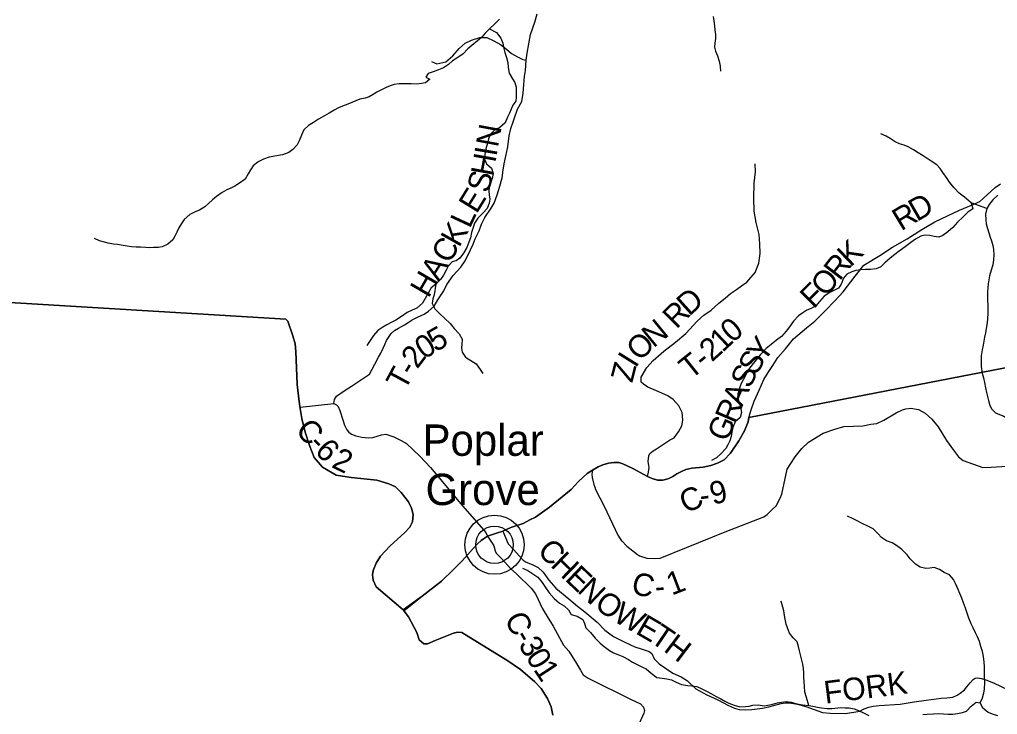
# Model space of a CAD drawing. Extents: x 1578669 to 1989827, y 208020 to 553079.
# Drawn here: x 1733554 to 1746556, y 378964 to 388207 of the extents above; entities that cross this region are included whole.
import ezdxf

# ---------------------------------------------------------------- set-up
doc = ezdxf.new("R2010")
doc.units = 0
for name, color, linetype in [('GM_X_Adjacent_County', 7, 'Continuous'), ('GM_X_County', 7, 'Continuous'), ('GM_X_County_Road', 7, 'Continuous'), ('GM_X_County_Road_Text', 7, 'Continuous'), ('GM_X_Minor_River', 7, 'Continuous'), ('GM_X_Township', 7, 'Continuous'), ('GM_X_Township_Road', 7, 'Continuous'), ('GM_X_Township_Road_Text', 7, 'Continuous'), ('GM_X_Unincorporated', 7, 'Continuous'), ('GM_X_Unincorporated_Location', 7, 'Continuous'), ('GM_X_Unincorporated_Text', 7, 'Continuous')]:
    doc.layers.add(name, color=color, linetype=linetype)

msp = doc.modelspace()

# ---------------------------------------------------------------- linework, layer by layer
at = {"layer": 'GM_X_Adjacent_County'}
msp.add_lwpolyline([(1733054, 384466), (1737094, 384224), (1737122, 384196), (1737189, 383999), (1737217, 383893), (1737228, 383790), (1737245, 383351), (1737272, 383125), (1737282, 383062), (1737309, 382900), (1737352, 382721), (1737408, 382543), (1737471, 382382), (1737581, 382255), (1737763, 382149), (1737961, 382114), (1738306, 382082), (1738462, 382031), (1738552, 381991), (1738628, 381917), (1738723, 381794), (1738765, 381710), (1738789, 381625), (1738780, 381525), (1738744, 381457), (1738678, 381385), (1738477, 381203), (1738354, 381068), (1738297, 380978), (1738257, 380880), (1738247, 380819), (1738256, 380749), (1738296, 380661), (1738653, 380354), (1738727, 380263), (1738834, 380056), (1738869, 379957), (1738928, 379905), (1738978, 379902), (1739079, 379949), (1739322, 380047), (1739378, 380057), (1739434, 380055), (1740048, 379676), (1740214, 379563), (1740405, 379400), (1740489, 379311), (1740575, 379176), (1740620, 379064), (1740644, 378956)], dxfattribs=at)
at = {"layer": 'GM_X_County'}
msp.add_lwpolyline([(1740644, 378956), (1740620, 379064), (1740575, 379176), (1740489, 379311), (1740405, 379400), (1740214, 379563), (1740048, 379676), (1739434, 380055), (1739378, 380057), (1739322, 380047), (1739079, 379949), (1738978, 379902), (1738928, 379905), (1738869, 379957), (1738834, 380056), (1738727, 380263), (1738653, 380354), (1738296, 380661), (1738256, 380749), (1738247, 380819), (1738257, 380880), (1738297, 380978), (1738354, 381068), (1738477, 381203), (1738678, 381385), (1738744, 381457), (1738780, 381525), (1738789, 381625), (1738765, 381710), (1738723, 381794), (1738628, 381917), (1738552, 381991), (1738462, 382031), (1738306, 382082), (1737961, 382114), (1737763, 382149), (1737581, 382255), (1737471, 382382), (1737408, 382543), (1737352, 382721), (1737309, 382900), (1737282, 383062), (1737272, 383125), (1737245, 383351), (1737228, 383790), (1737217, 383893), (1737189, 383999), (1737122, 384196), (1737094, 384224), (1733054, 384466)], dxfattribs=at)
at = {"layer": 'GM_X_County_Road'}
for points in [[(1743283, 383014), (1743321, 383133), (1743389, 383278), (1743449, 383418), (1743509, 383512), (1743569, 383606), (1743638, 383711), (1743736, 383829), (1743846, 383959), (1744016, 384106), (1744126, 384196), (1744266, 384334), (1744393, 384465), (1744505, 384587), (1744665, 384794), (1744779, 384940), (1744991, 385070), (1745162, 385181), (1745358, 385289), (1745552, 385416), (1745722, 385518), (1745894, 385598), (1746051, 385670), (1746211, 385737), (1746323, 385785), (1746419, 385877), (1746527, 385971), (1746599, 386022)], [(1737284, 383051), (1737732, 383098), (1737769, 383082), (1737792, 383061), (1737813, 383009), (1737850, 382885), (1737874, 382810), (1737904, 382751), (1737934, 382718), (1737967, 382694), (1738027, 382668), (1738106, 382651), (1738193, 382645), (1738251, 382648), (1738365, 382684), (1738422, 382690), (1738528, 382655), (1738626, 382610), (1738698, 382566), (1738876, 382399), (1739016, 382249), (1739133, 382112), (1739415, 381768), (1739752, 381384), (1739777, 381335)], [(1739777, 381335), (1739894, 381374), (1739980, 381400), (1740086, 381449), (1740251, 381505), (1740340, 381551), (1740412, 381587), (1740599, 381723), (1740889, 381958), (1740984, 382061), (1741046, 382119), (1741103, 382167), (1741172, 382213), (1741245, 382257), (1741309, 382286), (1741383, 382306), (1741456, 382315), (1741521, 382315), (1741577, 382296), (1741709, 382236), (1741905, 382129), (1741967, 382104), (1742038, 382081), (1742108, 382079), (1742144, 382088), (1742189, 382104), (1742238, 382130), (1742292, 382164), (1742357, 382196), (1742414, 382223), (1742493, 382238), (1742643, 382255), (1742744, 382275), (1742774, 382286), (1742841, 382309), (1742924, 382353), (1743005, 382441), (1743117, 382602), (1743191, 382737), (1743243, 382856), (1743250, 382913), (1743283, 383014)], [(1741172, 382213), (1741163, 382162), (1741167, 382118), (1741190, 382023), (1741201, 381989), (1741212, 381955), (1741328, 381734), (1741509, 381347), (1741559, 381274), (1741563, 381274), (1741627, 381203), (1741707, 381142), (1741770, 381091), (1741798, 381074), (1741894, 381043), (1742001, 381038), (1742073, 381042), (1742420, 381183), (1742934, 381391), (1743452, 381592), (1743496, 381624), (1743563, 381691), (1743613, 381737), (1743669, 381839), (1743688, 381894), (1743760, 382225), (1743810, 382300), (1743868, 382390), (1743956, 382503), (1744046, 382585), (1744241, 382705), (1744393, 382760), (1744514, 382792), (1744641, 382800), (1744767, 382803), (1744874, 382823), (1744951, 382835), (1745044, 382878), (1745210, 382976), (1745294, 383016), (1745340, 383028), (1745403, 383036), (1745507, 383022), (1745596, 382973), (1745682, 382892), (1745768, 382789), (1745881, 382607), (1745970, 382478), (1746039, 382389), (1746099, 382340), (1746364, 382251), (1746473, 382254), (1746830, 382274)], [(1739980, 381400), (1740052, 381232), (1740124, 381155), (1740197, 381076), (1740250, 381015), (1740291, 380990), (1740368, 380960), (1740448, 380918), (1740517, 380857), (1740593, 380750), (1740683, 380642), (1740857, 380501), (1740971, 380406), (1741069, 380330), (1741233, 380191), (1741335, 380086), (1741450, 380003), (1741584, 379934), (1741677, 379889), (1741733, 379862), (1741834, 379832), (1741927, 379802), (1741959, 379777), (1741993, 379703), (1742060, 379637), (1742242, 379514), (1742353, 379466), (1742433, 379411), (1742548, 379307), (1742691, 379226), (1742839, 379160), (1742982, 379081), (1743059, 379046), (1743124, 379031), (1743203, 379026), (1743289, 379032), (1743433, 379048), (1743517, 379065), (1743613, 379092), (1743682, 379110), (1743738, 379120), (1743791, 379118), (1743896, 379100), (1744010, 379070), (1744230, 378992), (1744332, 378982), (1744537, 378976), (1744728, 379008), (1744784, 379039), (1744844, 379061), (1744902, 379073), (1744984, 379083), (1745264, 379103), (1745449, 379130), (1745609, 379154), (1745807, 379182), (1745883, 379183), (1745963, 379196), (1746021, 379219), (1746061, 379248), (1746117, 379290), (1746151, 379332), (1746194, 379385), (1746233, 379431), (1746261, 379445), (1746291, 379452), (1746346, 379441), (1746413, 379419), (1746513, 379379), (1746691, 379298)], [(1738663, 380341), (1738909, 380539), (1739166, 380736), (1739329, 380897), (1739437, 381008), (1739586, 381172), (1739646, 381239), (1739690, 381276), (1739723, 381298), (1739777, 381335)], [(1739777, 381335), (1739839, 381241), (1739858, 381207), (1739877, 381139), (1739893, 381108), (1739970, 381030), (1740080, 380905), (1740164, 380828), (1740356, 380644), (1740414, 380567), (1740450, 380493), (1740502, 380378), (1740571, 380265), (1740649, 380137), (1740788, 379887), (1740856, 379805), (1740961, 379641), (1741014, 379554), (1741049, 379491), (1741113, 379445), (1741687, 379162), (1741809, 379104), (1741850, 379063), (1741863, 379017), (1741855, 378983), (1741795, 378854)]]:
    msp.add_lwpolyline(points, dxfattribs=at)
at = {"layer": 'GM_X_Minor_River'}
for points in [[(1739936, 388213), (1739874, 388151), (1739804, 388083), (1739746, 388024), (1739702, 387972), (1739644, 387922), (1739568, 387862), (1739516, 387817), (1739454, 387753), (1739380, 387703), (1739312, 387656), (1739257, 387610), (1739189, 387564), (1739122, 387538), (1739052, 387513), (1738986, 387491), (1738956, 387441), (1739011, 387415), (1738953, 387365), (1738899, 387357), (1738834, 387348), (1738762, 387352), (1738680, 387354), (1738600, 387350), (1738536, 387342), (1738482, 387325), (1738428, 387303), (1738364, 387271), (1738306, 387243), (1738256, 387212), (1738200, 387180), (1738150, 387162), (1738080, 387146), (1738026, 387128), (1737970, 387105), (1737918, 387083), (1737847, 387055), (1737795, 387031), (1737739, 387002), (1737671, 386964), (1737607, 386928), (1737529, 386884)], [(1742777, 388246), (1742787, 388188), (1742793, 388124), (1742799, 388068), (1742806, 388006), (1742808, 387954), (1742800, 387894), (1742796, 387839), (1742806, 387787), (1742836, 387723), (1742855, 387653), (1742871, 387587), (1742873, 387519)], [(1739804, 388083), (1739895, 388033), (1739955, 387961), (1739979, 387891), (1739993, 387821), (1740005, 387767), (1740030, 387701), (1740048, 387635), (1740052, 387569), (1740064, 387494), (1740108, 387420), (1740139, 387368), (1740157, 387308), (1740159, 387242), (1740155, 387176), (1740151, 387122), (1740113, 387068), (1740089, 387016), (1740068, 386963), (1740042, 386907), (1740010, 386835), (1739938, 386771), (1739872, 386742), (1739814, 386682), (1739790, 386620), (1739774, 386562), (1739754, 386488), (1739738, 386415), (1739736, 386351), (1739763, 386287), (1739829, 386229), (1739851, 386161), (1739839, 386093), (1739815, 386035), (1739800, 385981), (1739794, 385925), (1739800, 385875), (1739806, 385819), (1739800, 385764), (1739770, 385696), (1739718, 385634), (1739646, 385564), (1739604, 385497), (1739585, 385443), (1739565, 385373), (1739549, 385305), (1739529, 385245), (1739499, 385176), (1739455, 385100), (1739409, 385032), (1739357, 384998), (1739307, 384985), (1739253, 384925), (1739227, 384873), (1739189, 384807), (1739152, 384748), (1739088, 384688), (1739028, 384638), (1738986, 384568), (1738948, 384497), (1738912, 384433), (1738834, 384369), (1738772, 384342), (1738706, 384310), (1738634, 384258), (1738558, 384210), (1738494, 384177), (1738436, 384147), (1738384, 384117), (1738316, 384071), (1738262, 384006), (1738216, 383938), (1738172, 383870)], [(1737529, 386884), (1737461, 386837), (1737395, 386797), (1737335, 386739), (1737304, 386670), (1737270, 386596), (1737246, 386540), (1737188, 386478), (1737132, 386440), (1737052, 386407), (1736998, 386397), (1736948, 386391), (1736874, 386375), (1736799, 386352), (1736727, 386316), (1736659, 386262), (1736626, 386208), (1736594, 386153), (1736552, 386085), (1736478, 386029), (1736414, 385990), (1736364, 385966), (1736310, 385942), (1736248, 385908), (1736174, 385855), (1736120, 385807), (1736068, 385759), (1736016, 385717), (1735948, 385670), (1735888, 385648), (1735816, 385612), (1735742, 385546), (1735706, 385495), (1735672, 385435), (1735644, 385377), (1735620, 385327), (1735590, 385275), (1735524, 385218), (1735450, 385184), (1735400, 385176), (1735334, 385174), (1735284, 385171), (1735232, 385175), (1735160, 385179), (1735106, 385181), (1735043, 385185), (1734985, 385193), (1734931, 385202), (1734857, 385214), (1734803, 385220), (1734733, 385232), (1734683, 385244), (1734615, 385264), (1734548, 385293)], [(1746416, 385694), (1746206, 385767), (1746119, 385846), (1746049, 385896), (1745983, 385967), (1745920, 386045), (1745886, 386095), (1745832, 386172), (1745795, 386226), (1745749, 386276), (1745677, 386325), (1745623, 386359), (1745568, 386395), (1745502, 386434), (1745440, 386476), (1745368, 386515), (1745314, 386537), (1745255, 386555), (1745197, 386582), (1745129, 386624), (1745077, 386654), (1745005, 386689)], [(1746563, 385873), (1746496, 385808), (1746444, 385748), (1746416, 385694), (1746397, 385620), (1746401, 385544), (1746407, 385488), (1746422, 385428), (1746442, 385369), (1746460, 385313), (1746477, 385263), (1746495, 385203), (1746503, 385151), (1746508, 385075), (1746504, 385013), (1746493, 384943), (1746471, 384873), (1746451, 384799), (1746440, 384743), (1746434, 384691), (1746425, 384587), (1746423, 384537), (1746423, 384477), (1746428, 384404), (1746430, 384350), (1746428, 384298), (1746423, 384232), (1746419, 384172), (1746408, 384098), (1746398, 384038), (1746386, 383982), (1746377, 383930), (1746365, 383874), (1746351, 383812), (1746342, 383732), (1746340, 383668), (1746341, 383594), (1746355, 383504), (1746369, 383440), (1746382, 383378), (1746398, 383307), (1746411, 383247)], [(1746206, 385767), (1746230, 385691), (1746161, 385645), (1746099, 385582), (1746027, 385510), (1745962, 385442), (1745896, 385384), (1745830, 385333), (1745779, 385313), (1745713, 385321), (1745659, 385334), (1745591, 385338), (1745537, 385324), (1745467, 385285), (1745405, 385241), (1745328, 385183), (1745248, 385128), (1745194, 385084), (1745130, 385032), (1745061, 384969), (1745007, 384919), (1744943, 384893), (1744867, 384884), (1744803, 384884), (1744739, 384880), (1744674, 384869), (1744618, 384851), (1744552, 384819), (1744510, 384768), (1744477, 384688), (1744445, 384636), (1744391, 384608), (1744329, 384576), (1744254, 384529), (1744190, 384455), (1744142, 384399), (1744081, 384363), (1744021, 384340), (1743967, 384308), (1743909, 384264), (1743844, 384195), (1743790, 384121), (1743745, 384063), (1743685, 383993), (1743617, 383944), (1743546, 383886), (1743482, 383830), (1743404, 383753), (1743347, 383683), (1743307, 383631), (1743244, 383551), (1743175, 383415), (1743145, 383357), (1743125, 383304), (1743104, 383230), (1743104, 383178), (1743120, 383109), (1743139, 383055), (1743153, 382981), (1743134, 382913), (1743068, 382857), (1743036, 382781), (1743023, 382717), (1743015, 382659), (1742999, 382605), (1742972, 382551), (1742944, 382500), (1742880, 382430), (1742819, 382376), (1742755, 382340)], [(1739088, 384688), (1739068, 384546), (1739048, 384494), (1739038, 384429), (1739074, 384359), (1739137, 384298), (1739205, 384236), (1739281, 384164), (1739333, 384096), (1739400, 384028), (1739438, 383954), (1739436, 383886), (1739432, 383836), (1739438, 383783), (1739483, 383717), (1739555, 383672), (1739623, 383626), (1739679, 383554), (1739712, 383498)], [(1746411, 383247), (1746423, 383195), (1746437, 383141), (1746456, 383073), (1746480, 383023), (1746532, 382978), (1746584, 382952), (1746640, 382930), (1746715, 382885)], [(1746327, 379118), (1746357, 379186), (1746376, 379250), (1746384, 379302), (1746387, 379390), (1746383, 379479), (1746382, 379539), (1746382, 379601), (1746378, 379661), (1746373, 379735), (1746357, 379803), (1746337, 379869), (1746316, 379936), (1746290, 379998), (1746266, 380048), (1746233, 380118), (1746205, 380168), (1746174, 380247), (1746152, 380313), (1746130, 380377), (1746103, 380449), (1746081, 380510), (1746058, 380572), (1746034, 380628), (1745998, 380704), (1745973, 380759), (1745919, 380823), (1745847, 380853), (1745785, 380892), (1745715, 380918), (1745659, 380908), (1745605, 380907), (1745529, 380923), (1745466, 380964), (1745396, 381036), (1745358, 381086), (1745283, 381157), (1745213, 381213), (1745155, 381246), (1745083, 381274), (1745016, 381319), (1744964, 381373), (1744902, 381431), (1744834, 381470), (1744757, 381506), (1744691, 381539), (1744639, 381567), (1744563, 381601)], [(1740242, 380909), (1740310, 380880), (1740379, 380834), (1740443, 380789), (1740501, 380721), (1740548, 380652), (1740594, 380582), (1740660, 380506), (1740731, 380443), (1740795, 380407), (1740851, 380356), (1740886, 380294), (1740966, 380270), (1741042, 380225), (1741064, 380173), (1741083, 380117), (1741147, 380056), (1741209, 379980), (1741272, 379914), (1741326, 379869), (1741398, 379813), (1741452, 379784), (1741507, 379760), (1741573, 379736), (1741649, 379697), (1741703, 379661), (1741757, 379632), (1741829, 379598), (1741886, 379572), (1741954, 379513), (1742028, 379457), (1742096, 379446), (1742162, 379440), (1742224, 379426), (1742284, 379395), (1742355, 379363), (1742435, 379348), (1742491, 379346), (1742561, 379334), (1742617, 379311), (1742687, 379275), (1742753, 379240), (1742815, 379202), (1742878, 379172), (1742932, 379139), (1742986, 379115), (1743056, 379087), (1743130, 379066), (1743204, 379068), (1743254, 379075), (1743304, 379087), (1743374, 379091), (1743456, 379080), (1743528, 379092), (1743582, 379106), (1743632, 379119), (1743686, 379127), (1743748, 379137), (1743814, 379128), (1743888, 379106), (1743962, 379092), (1744048, 379081), (1744102, 379075), (1744162, 379062), (1744216, 379052), (1744294, 379042), (1744354, 379043), (1744474, 379055), (1744532, 379054), (1744584, 379052), (1744650, 379038), (1744710, 379017), (1744782, 378983), (1744844, 378952)], [(1744048, 379081), (1744019, 379189), (1743997, 379260), (1743992, 379342), (1743988, 379394), (1743984, 379462), (1743983, 379518), (1743979, 379574), (1743969, 379634), (1743938, 379759), (1743926, 379811), (1743913, 379869), (1743895, 379929), (1743841, 379983), (1743792, 380044), (1743766, 380116), (1743748, 380166), (1743733, 380232), (1743723, 380282), (1743714, 380343), (1743702, 380393), (1743680, 380473)], [(1745562, 378962), (1745622, 378970), (1745706, 378974), (1745776, 378977), (1745840, 378971), (1745900, 378967), (1745964, 378968), (1746026, 378978), (1746092, 378989), (1746146, 379009), (1746205, 379075), (1746275, 379127), (1746327, 379118), (1746353, 379060), (1746432, 378996), (1746488, 378971), (1746556, 378949)]]:
    msp.add_lwpolyline(points, dxfattribs=at)
at = {"layer": 'GM_X_Township'}
for points in [[(1752267, 384661), (1743250, 382913), (1743243, 382856), (1743191, 382737), (1743117, 382602), (1743005, 382441), (1742924, 382353), (1742841, 382309), (1742774, 382286), (1742744, 382275), (1742643, 382255), (1742493, 382238), (1742414, 382223), (1742357, 382196), (1742292, 382164), (1742238, 382130), (1742189, 382104), (1742144, 382088), (1742108, 382079), (1742038, 382081), (1741967, 382104), (1741905, 382129), (1741709, 382236), (1741577, 382296), (1741521, 382315), (1741456, 382315), (1741383, 382306), (1741309, 382286), (1741245, 382257), (1741172, 382213), (1741103, 382167), (1741046, 382119), (1740984, 382061), (1740889, 381958), (1740599, 381723), (1740412, 381587), (1740340, 381551), (1740251, 381505), (1740086, 381449), (1739980, 381400), (1739895, 381374), (1739777, 381335), (1739723, 381298), (1739690, 381276), (1739646, 381239), (1739586, 381172), (1739437, 381008), (1739329, 380897), (1739166, 380736), (1738909, 380539), (1738653, 380354), (1738296, 380661), (1738256, 380749), (1738247, 380819), (1738257, 380880), (1738297, 380978), (1738354, 381068), (1738477, 381203), (1738678, 381385), (1738744, 381457), (1738780, 381525), (1738789, 381625), (1738765, 381710), (1738723, 381794), (1738628, 381917), (1738552, 381991), (1738462, 382031), (1738306, 382082), (1737961, 382114), (1737763, 382149), (1737581, 382255), (1737471, 382382), (1737408, 382543), (1737352, 382721), (1737309, 382900), (1737282, 383062), (1737272, 383125), (1737245, 383351), (1737228, 383790), (1737217, 383893), (1737189, 383999), (1737122, 384196), (1737094, 384224), (1733054, 384466)], [(1740644, 378956), (1740620, 379064), (1740575, 379176), (1740489, 379311), (1740405, 379400), (1740214, 379563), (1740048, 379676), (1739434, 380055), (1739378, 380057), (1739322, 380047), (1739079, 379949), (1738978, 379902), (1738928, 379905), (1738869, 379957), (1738834, 380056), (1738727, 380263), (1738653, 380354), (1738909, 380539), (1739166, 380736), (1739329, 380897), (1739437, 381008), (1739586, 381172), (1739646, 381239), (1739690, 381276), (1739723, 381298), (1739777, 381335), (1739895, 381374), (1739980, 381400), (1740086, 381449), (1740251, 381505), (1740340, 381551), (1740412, 381587), (1740599, 381723), (1740889, 381958), (1740984, 382061), (1741046, 382119), (1741103, 382167), (1741172, 382213), (1741245, 382257), (1741309, 382286), (1741383, 382306), (1741456, 382315), (1741521, 382315), (1741577, 382296), (1741709, 382236), (1741905, 382129), (1741967, 382104), (1742038, 382081), (1742108, 382079), (1742144, 382088), (1742189, 382104), (1742238, 382130), (1742292, 382164), (1742357, 382196), (1742414, 382223), (1742493, 382238), (1742643, 382255), (1742744, 382275), (1742774, 382286), (1742841, 382309), (1742924, 382353), (1743005, 382441), (1743117, 382602), (1743191, 382737), (1743243, 382856), (1743250, 382913), (1752267, 384661)]]:
    msp.add_lwpolyline(points, dxfattribs=at)
at = {"layer": 'GM_X_Township_Road'}
for points in [[(1739981, 386178), (1739999, 386286), (1740021, 386391), (1740044, 386515), (1740062, 386661), (1740084, 386757), (1740116, 386846), (1740136, 386900), (1740174, 387016), (1740230, 387118), (1740248, 387230), (1740259, 387343), (1740269, 387449), (1740281, 387529), (1740289, 387665), (1740305, 387759), (1740349, 388010), (1740407, 388174), (1740438, 388285)], [(1739030, 387648), (1739102, 387618), (1739223, 387646), (1739315, 387726), (1739401, 387821), (1739477, 387891), (1739565, 387933), (1739673, 387969), (1739767, 387967), (1739861, 387925), (1739949, 387873), (1740029, 387815), (1740095, 387757), (1740175, 387711), (1740245, 387677), (1740289, 387665)], [(1741905, 382129), (1741918, 382185), (1741925, 382251), (1741913, 382328), (1741919, 382403), (1741935, 382433), (1741977, 382471), (1742021, 382497), (1742091, 382541), (1742194, 382613), (1742258, 382645), (1742314, 382723), (1742358, 382804), (1742372, 382878), (1742362, 382980), (1742319, 383068), (1742245, 383154), (1742173, 383202), (1742025, 383270), (1741909, 383318), (1741849, 383358), (1741821, 383386), (1741819, 383452), (1741893, 383581), (1741977, 383671), (1742121, 383795), (1742275, 383914), (1742414, 384030), (1742562, 384195), (1742652, 384275), (1742748, 384343), (1742850, 384433), (1742934, 384499), (1743006, 384564), (1743086, 384616), (1743154, 384664), (1743223, 384714), (1743335, 384841), (1743385, 384965), (1743401, 385095), (1743397, 385223), (1743387, 385350), (1743347, 385506), (1743322, 385660), (1743318, 385830), (1743320, 386029), (1743330, 386105), (1743340, 386183), (1743334, 386287)], [(1737732, 383098), (1737741, 383152), (1737769, 383198), (1737810, 383230), (1737825, 383239), (1737885, 383279), (1737969, 383331), (1738208, 383490), (1738276, 383624), (1738328, 383718), (1738358, 383770), (1738390, 383836), (1738410, 383884), (1738434, 383936), (1738466, 383991), (1738496, 384029), (1738540, 384071), (1738592, 384103), (1738671, 384145), (1738719, 384179), (1738775, 384215), (1738847, 384249), (1738933, 384290), (1738993, 384326), (1739067, 384394), (1739117, 384480), (1739195, 384598), (1739237, 384685), (1739317, 384803), (1739420, 384915), (1739478, 384999), (1739548, 385142), (1739586, 385220), (1739612, 385292), (1739664, 385398), (1739698, 385487), (1739740, 385573), (1739825, 385699), (1739863, 385765), (1739903, 385875), (1739939, 385990), (1739969, 386100), (1739980, 386169), (1739981, 386178)]]:
    msp.add_lwpolyline(points, dxfattribs=at)
at = {"layer": 'GM_X_Unincorporated'}
for radius in [393, 249]:
    msp.add_circle((1739869, 381221), radius, dxfattribs=at)
at = {"layer": 'GM_X_Unincorporated_Location'}
msp.add_line((1739869, 381221), (1739869, 381221), dxfattribs=at)

# ---------------------------------------------------------------- texts
at = {"layer": 'GM_X_County_Road_Text'}
for s, rotation, p in [('D', 29.9017, (1745485, 385514)), ('R', 31.0468, (1745275, 385388)), ('K', 43.6914, (1744602, 384906)), ('R', 52.1867, (1744459, 384720)), ('O', 48.2819, (1744269, 384506)), ('F', 45.0907, (1744113, 384349)), ('Y', 54.8731, (1743447, 383632)), ('S', 59.4135, (1743347, 383463)), ('S', 64.9481, (1743265, 383287)), ('A', 66.7488, (1743162, 383046)), ('R', 66.8214, (1743065, 382820)), ('C', 313.2638, (1737208, 382729)), ('G', 66.8239, (1742961, 382577)), ('-', 313.4671, (1737378, 382549)), ('6', 314.6357, (1737467, 382455)), ('2', 334.2557, (1737688, 382258)), ('9', 14.2704, (1742773, 381750)), ('C', 23.4881, (1742409, 381634)), ('-', 7.5307, (1742613, 381727)), ('C', 314.1444, (1740424, 381126)), ('H', 315.875, (1740602, 380942)), ('E', 316.4056, (1740794, 380756)), ('C', 347.4936, (1741674, 380574)), ('1', 20.916, (1742225, 380544)), ('N', 316.6988, (1740958, 380600)), ('-', 4.3301, (1742010, 380514)), ('O', 323.8765, (1741182, 380393)), ('W', 330.9771, (1741429, 380215)), ('C', 296.7344, (1739995, 380239)), ('E', 329.7698, (1741731, 380048)), ('T', 326.0473, (1741921, 379937)), ('-', 300.4797, (1740116, 380000)), ('3', 300.4568, (1740179, 379894)), ('H', 322.8758, (1742104, 379815)), ('0', 301.713, (1740276, 379729)), ('1', 303.4407, (1740379, 379563)), ('FORK', 7.1027, (1744268, 379107))]:
    msp.add_text(s, height=300, rotation=rotation, dxfattribs=at).set_placement(p)
at = {"layer": 'GM_X_Township_Road_Text'}
for s, rotation, p in [('N', 79.5681, (1739914, 386498)), ('I', 80.6465, (1739895, 386378)), ('H', 79.648, (1739846, 386112)), ('S', 74.3122, (1739785, 385888)), ('E', 58.3203, (1739630, 385613)), ('L', 65.0416, (1739540, 385418)), ('K', 60.4965, (1739398, 385165)), ('C', 58.8542, (1739266, 384946)), ('A', 57.8185, (1739122, 384718)), ('H', 59.7491, (1738990, 384492)), ('D', 41.8559, (1742457, 384252)), ('R', 45.2144, (1742287, 384081)), ('0', 41.0337, (1743034, 383897)), ('5', 30.0373, (1739085, 383778)), ('N', 39.2048, (1741982, 383831)), ('0', 32.7793, (1738933, 383679)), ('O', 44.5441, (1741800, 383651)), ('2', 42.2525, (1742760, 383644)), ('1', 43.3411, (1742902, 383772)), ('2', 52.7846, (1738841, 383551)), ('I', 58.0683, (1741746, 383561)), ('T', 38.7267, (1742476, 383411)), ('-', 40.0133, (1742656, 383556)), ('T', 61.4874, (1738676, 383259)), ('-', 58.4365, (1738781, 383452)), ('Z', 75.6831, (1741700, 383366))]:
    msp.add_text(s, height=300, rotation=rotation, dxfattribs=at).set_placement(p)
at = {"layer": 'GM_X_Unincorporated_Text'}
for s, p in [('Poplar', (1738912, 382404)), ('Grove', (1738952, 381749))]:
    msp.add_text(s, height=417, rotation=0, dxfattribs=at).set_placement(p)

doc.saveas('drawing.dxf')
